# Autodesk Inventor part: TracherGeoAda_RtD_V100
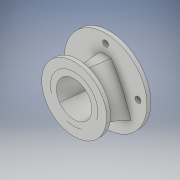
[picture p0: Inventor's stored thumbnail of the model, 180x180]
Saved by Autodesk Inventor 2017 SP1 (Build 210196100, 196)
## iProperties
Part Number: TracherGeoAda_RtD_V100
Material: Generisch
Document SubType Name: Modeling
Designer: haesner
Density: 1 g/cm^3
Appearance: Vorgabe
Author: haesner
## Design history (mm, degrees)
sketch "Skizze1"
  geometry: C1 r 9 at (0, 0); 1 further point
  constraints: 1 centre point, 1 coincident
  dimensions: "d0" = 18 diameter of C1
workplane "Arbeitsebene1"
sketch "Skizze2"
  geometry: L1 (1, 8.5)-(-1, 8.5); L2 (-1, 8.5)-(-8.927, -8.5); L3 (-8.927, -8.5)-(8.927, -8.5); L4 (8.927, -8.5)-(1, 8.5); L5 (12.498, 0)-(-12.498, 0) reference; L6 (0, -11.9)-(0, 11.9) reference
  constraints: 8 end point, 2 symmetric about line, 1 horizontal, 1 parallel, 1 other
  dimensions: "d22" = 2 distance of L1.start L1.end; "d23" = 17 distance between parallel lines of L3 L1; "d24" = 25 deg angle of L6 L2
feature "Erhebung1" sketch "Skizze2" dims "d3" = 0, "d4" = 90 deg, "d5" = 0, "d6" = 90 deg
feature "Wandung1" dims "d7" = 3
sketch "Skizze3"
  geometry: C1 r 16.5 at (-1.303, -11.894); 4 further points
  constraints: 1 centre point, 4 other
  dimensions: "d8" = 33 diameter of C1
extrude "Extrusion1" join sketch "Skizze3" distance "d9" = 2; taper "d10" = 0 deg
sketch "Skizze4"
  geometry: L1 (-8.723, 20.604)-(9.13, 20.427) reference; L2 (9.13, 20.427)-(1.035, 3.507) reference; L3 (1.035, 3.507)-(-0.965, 3.526) reference; L4 (-0.965, 3.526)-(-8.723, 20.604) reference; C1 r 21 at (0.119, 12.016); 1 further point
  constraints: 1 centre point, 1 coincident
  dimensions: "d25" = 42 diameter of C1
extrude "Extrusion2" join sketch "Skizze4" distance "d12" = 2; taper "d13" = 0 deg
sketch "Skizze5"
  geometry: L1 (-16.5, 0)-(0, -16.5); L2 (0, -16.5)-(16.5, 0); L3 (16.5, 0)-(0, 16.5); L4 (0, 16.5)-(-16.5, 0); L5 (-29.4, 0)-(29.4, 0) reference; L6 (0, 29.4)-(0, -29.4) reference; 1 further point
  constraints: 8 end point, 3 point on line, 2 parallel, 2 perpendicular
  dimensions: "d14" = 16.5 distance from line of L1.start L6
hole "Bohrung1" sketch "Skizze5" at (-16.5, 0), (0, 16.5), (16.5, 0), (0, -16.5) diameter "d15" = 3; stored, may be unused: countersink angle "d19" = 90 deg, drill point angle "d21" = 118 deg; dims "d16" = 6, "d17" = 4, "d18" = 2, "d20" = 8
node "Volumenkörper1"
other parameters: "d1" = 18
